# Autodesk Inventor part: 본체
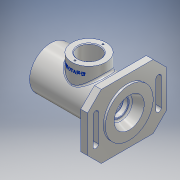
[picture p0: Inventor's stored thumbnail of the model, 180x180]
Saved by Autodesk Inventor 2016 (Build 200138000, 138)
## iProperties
Created: 2017-10
Part Number: 본체
Material: 알루미늄 6061
Document SubType Name: Modeling
Designer: USER
Density: 2.7 g/cm^3
Appearance: 알루미늄 - 평지
Mass: 735.583 g
Surface Area: 651.612 cm^2
Volume: 272.438 cm^3
Author: USER
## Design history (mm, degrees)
sketch "스케치1"
  geometry: L1 (-38, 47)-(38, 47); L2 (58, 27)-(58, -27); L3 (38, -47)-(-38, -47); L4 (-58, -27)-(-58, 27); L5 (-38, 47)-(-58, 27); L6 (38, 47)-(58, 27); L7 (-58, -27)-(-38, -47); L8 (58, -27)-(38, -47); L9 (-46, 20)-(-46, -20); L10 (-50, 20)-(-50, -20); L11 (-42, -20)-(-42, 20); L12 (46, 20)-(46, -20); L13 (42, 20)-(42, -20); L14 (50, -20)-(50, 20); A1 r 4 centre (-46, 20) between (-42, 20) and (-50, 20); A2 r 4 centre (-46, -20) between (-50, -20) and (-42, -20); A3 r 4 centre (46, 20) between (50, 20) and (42, 20); A4 r 4 centre (46, -20) between (42, -20) and (50, -20); 9 further points
  constraints: 32 end point, 8 point on circle, 8 point on line, 8 tangent, 4 centre point, 4 midpoint, 4 parallel, 3 horizontal alignment, 2 vertical, 1 horizontal, 1 perpendicular, 1 vertical alignment
  dimensions: "d4" = 116 distance of point (58, -47) point (-58, -47); "d5" = 94 distance of point (58, 47) point (58, -47); "d6" = 20 distance of L1.start point (-58, 47); "d7" = 20 distance of L4.end point (-58, 47) (= d6); "d8" = 20 distance of L1.end point (58, 47) (= d6); "d9" = 20 distance of L2.start point (58, 47) (= d8); "d10" = 20 distance of L4.start point (-58, -47) (= d6); "d11" = 20 distance of L3.end point (-58, -47) (= d10); "d12" = 20 distance of L2.end point (58, -47) (= d6); "d13" = 20 distance of L3.start point (58, -47) (= d12); "d14" = 8 diameter of A2; "d15" = 20 distance of L9.end point (-46, 0); "d16" = 46 distance of point (0, 0) point (-46, 0); "d18" = 8 diameter of A4; "d19" = 20 distance of L12.end point (46, 0); "d20" = 46 distance of point (0, 0) point (46, 0)
extrude "돌출1" new body sketch "스케치1" distance "d21" = 10; taper "d22" = 0 deg
sketch "스케치2"
  geometry: L1 (-47, 38)-(-47, -38) reference; C1 r 35 at (0, 0); 1 further point
  constraints: 1 centre point, 1 coincident
  dimensions: "d23" = 70 diameter of C1; "d24" = 47 distance from line of C1.centre L1
extrude "돌출2" join sketch "스케치2" distance "d25" = 3; taper "d26" = 0 deg
sketch "스케치3"
  geometry: C1 r 31 at (0, 0); 1 further point
  constraints: 1 centre point, 1 coincident
  dimensions: "d27" = 62 diameter of C1
extrude "돌출3" join sketch "스케치3" distance "d28" = 102; taper "d29" = 0 deg
node "작업 평면1"
sketch "스케치4"
  geometry: L1 (-112, 31)-(-112, -31) reference; L2 (-10, -31)-(-10, 31) reference; L3 (0, 38)-(0, -38) reference; C1 r 25 at (-56, 0); 2 further points
  constraints: 1 centre point, 1 horizontal alignment, 1 midpoint
  dimensions: "d31" = 50 diameter of C1; "d32" = 56 distance from line of C1.centre L1
extrude "돌출4" join sketch "스케치4" stored distance "d33" = 102; taper "d34" = 0 deg
sketch "스케치5"
  geometry: L1 (112, -31)-(112, 31) reference; L2 (10, 31)-(112, 31) reference; L3 (0, 27)-(0, 47) reference; L4 (0, 27)-(10, 27) reference; L5 (10, 47)-(10, 27) reference; L6 (0, 47)-(10, 47) reference; L7 (10, -31)-(112, -31) reference; L8 (0, -47)-(0, -27) reference; L9 (0, -47)-(10, -47) reference; L10 (10, -27)-(10, -47) reference; L11 (0, -27)-(10, -27) reference; L12 (-3, 35)-(-3, -35) reference; L13 (-33.492, 0)-(143.426, 0); L14 (112, 21)-(103, 21); L15 (103, 21)-(103, 24); L16 (103, 24)-(100, 24); L17 (100, 24)-(100, 20); L18 (100, 20)-(91, 20); L19 (91, 20)-(91, 17.5); L20 (91, 17.5)-(87.75, 17.5); L21 (87.75, 17.5)-(87.75, 18.5); L22 (87.75, 18.5)-(86, 18.5); L23 (86, 18.5)-(86, 17.5); L24 (86, 17.5)-(75, 17.5); L25 (75, 17.5)-(75, 26); L26 (75, 26)-(37, 26); L27 (37, 26)-(37, 17.5); L28 (37, 17.5)-(26, 17.5); L29 (26, 17.5)-(26, 17.5); L30 (26, 17.5)-(26, 16.5); L31 (26, 16.5)-(21, 16.5); L32 (21, 16.5)-(21, 10); L33 (21, 10)-(18.3, 10); L34 (18.3, 10)-(18.3, 12.5); L35 (18.3, 12.5)-(11, 12.5); L36 (11, 12.5)-(11, 16); L37 (11, 16)-(-3, 22); L38 (112, 21)-(112, 0); L39 (112, 0)-(-3, 0); L40 (-3, 22)-(-3, 0); 1 further point
  constraints: 56 end point, 19 perpendicular, 7 point on line, 2 horizontal, 2 midpoint, 2 vertical, 1 horizontal alignment
  dimensions: "d35" = 42 diameter of L14 L13; "d36" = 9 distance between parallel lines of L15 L38; "d37" = 3 distance between parallel lines of L17 L15; "d38" = 48 diameter of L16 L13; "d39" = 40 diameter of L18 L13; "d40" = 9 distance between parallel lines of L19 L17; "d41" = 35 diameter of L20 L13; "d42" = 3.25 distance from line of L21.end L19; "d43" = 37 diameter of L22 L13; "d44" = 1.75 distance between parallel lines of L23 L21; "d45" = 11 distance between parallel lines of L25 L23; "d46" = 52 diameter of L26 L13; "d47" = 38 distance between parallel lines of L27 L25; "d48" = 11 distance between parallel lines of L30 L27; "d49" = 5 distance between parallel lines of L32 L30; "d50" = 33 diameter of L31 L13; "d51" = 20 diameter of L33 L13; "d52" = 2.7 distance of L33.end L32.end; "d53" = 7.3 distance between parallel lines of L36 L34; "d54" = 25 diameter of L35 L13; "d55" = 44 diameter of L37.end L13; "d56" = 32 diameter of L36.end L13
revolve "회전1" sketch "스케치5" stored, may be unused: angle "d57" = 90 deg
sketch "스케치6"
  geometry: C1 r 25 at (0, 0) reference; C2 r 16 at (0, 0); 1 further point
  constraints: 1 centre point, 1 coincident
  dimensions: "d58" = 32 diameter of C2
extrude "돌출5" cut sketch "스케치6" stored distance "d59" = 102; taper "d60" = 0 deg
sketch "스케치7"
  geometry: C1 r 16 at (0, 0) reference; C2 r 25 at (0, 0) reference; 2 further points
  constraints: 1 vertical alignment
  dimensions: "d61" = 20.5 distance of C1.centre point (0, 20.5)
hole "구멍1" sketch "스케치7" at (0, 20.5) diameter "d62" = 2.459; stored, may be unused: countersink angle "d66" = 90 deg, drill point angle "d68" = 118 deg; dims "d63" = 6, "d64" = 4, "d65" = 2, "d67" = 8
fillet "모깎기1" dims "d72" = 3
feature "스레드1" dims "d73" = 10, "d74" = 0
chamfer "모따기1" distance "d75" = 1; stored, may be unused: second distance "d76" = 2, angle "d77" = 45 deg
chamfer "모따기2" distance "d78" = 1; stored, may be unused: second distance "d79" = 2, angle "d80" = 45 deg
fillet "모깎기2" dims "d81" = 3
chamfer "모따기3" distance "d82" = 1; stored, may be unused: second distance "d83" = 2, angle "d84" = 45 deg
fillet "모깎기3" dims "d85" = 0.3
fillet "모깎기4" dims "d86" = 3
fillet "모깎기5" dims "d87" = 3
chamfer "모따기4" distance "d88" = 0.7; stored, may be unused: second distance "d89" = 2, angle "d90" = 30 deg
fillet "모깎기6" dims "d91" = 0.3
node "작업 평면4"
chamfer "모따기5" distance "d101" = 1; stored, may be unused: second distance "d102" = 2, angle "d103" = 45 deg
sketch "스케치14"
  geometry: L1 (-25, 0)-(25, 0) reference; L2 (56, -78)-(56, -16) reference; 2 further points
  constraints: 1 other
  dimensions: "d110" = 10 distance from line of point (0, -10) L1; "d111" = 56 distance from line of L2 point (0, -10)
feature "엠보싱4" sketch "스케치14" dims "d4" = 116, "d5" = 94, "d6" = 20, "d7" = 20 (= d6), "d8" = 20 (= d6), "d9" = 20 (= d8), "d10" = 20 (= d6), "d11" = 20 (= d10), "d12" = 20 (= d6), "d13" = 20 (= d12), "d14" = 8, "d15" = 20, "d16" = 46, "d112" = 0.5, "d113" = 0
node "솔리드1"
pattern_circular "원형 패턴1" dims angle "d70" = 360 deg
node "투영된 루프1"
node "투영된 루프2"
node "투영된 루프3"
node "투영된 루프4"
node "투영된 루프5"
other parameters: "d30" = 47
